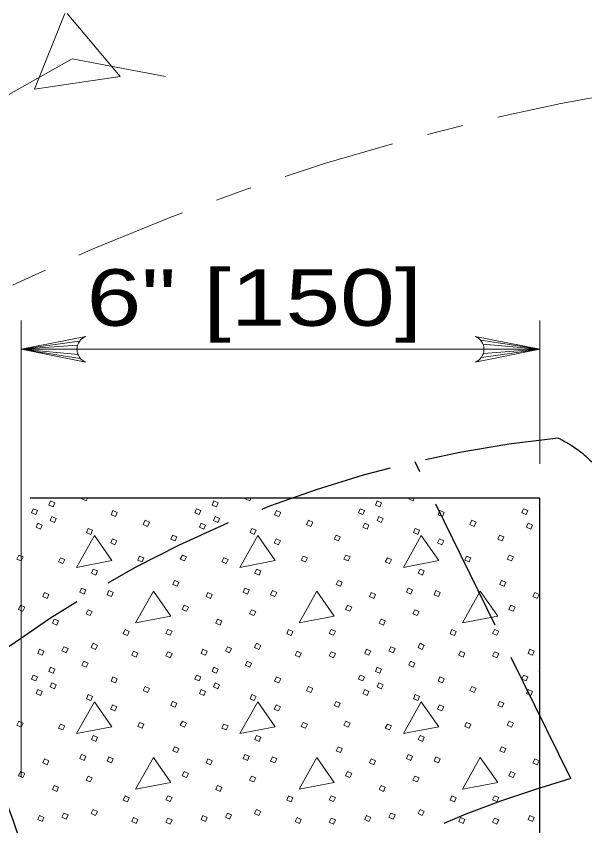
# Model space of a CAD drawing. Extents: x 1083.1 to 1117.1, y 719.4 to 741.4.
# Drawn here: x 1091.505 to 1093.074, y 727.471 to 729.705 of the extents above; entities that cross this region are included whole.
import ezdxf

# ---------------------------------------------------------------- set-up
doc = ezdxf.new("R2010")
doc.units = 0
doc.header["$LTSCALE"] = 0.062
doc.linetypes.add('DOT_DASHED', pattern=[7.7, 5, -1.2, 0.3, -1.2])
doc.linetypes.add('LONG_DASHED', pattern=[7.5, 6, -1.5])
doc.layers.add('1', color=7, linetype='Continuous', lineweight=13)

msp = doc.modelspace()

# ---------------------------------------------------------------- linework, layer by layer
at = {"layer": '1'}
for p, q in [((1091.65942, 729.58758), (1091.43975, 729.46433)), ((1091.65942, 729.58758), (1091.91658, 729.53892)), ((1091.51858, 727.60667), (1091.51858, 728.86525)), ((1092.94983, 728.47042), (1092.94983, 728.86525)), ((1091.67975, 728.80867), (1091.51858, 728.78608)), ((1091.67433, 728.7975), (1091.51858, 728.78608)), ((1092.78675, 728.811), (1092.94983, 728.78608)), ((1092.79292, 728.80058), (1092.94983, 728.78608)), ((1091.51858, 728.78608), (1092.94983, 728.78608)), ((1091.67267, 728.78608), (1091.51858, 728.78608)), ((1091.6755, 728.77167), (1091.51858, 728.78608)), ((1091.68167, 728.76117), (1091.51858, 728.78608)), ((1092.78867, 728.76358), (1092.94983, 728.78608)), ((1092.79408, 728.77475), (1092.94983, 728.78608)), ((1092.79575, 728.78608), (1092.94983, 728.78608))]:
    msp.add_line(p, q, dxfattribs=at)
at = {"layer": '1', "linetype": 'LONG_DASHED', "lineweight": 25}
msp.add_line((1093.0355, 727.60142), (1092.6055, 728.47533), dxfattribs=at)
at = {"layer": '1', "lineweight": 25}
msp.add_line((1092.94983, 728.3755), (1091.54342, 728.3755), dxfattribs=at)
at = {"layer": '1'}
for points in [[(1091.63858, 729.71292), (1091.55517, 729.50408), (1091.79142, 729.53892), (1091.6455, 729.71292)], [(1091.69667, 728.7505), (1091.51858, 728.78608), (1091.69667, 728.82175)], [(1092.77175, 728.82175), (1092.94983, 728.78608), (1092.77175, 728.7505)], [(1091.7015, 728.3755), (1091.69825, 728.368), (1091.68633, 728.3735), (1091.68725, 728.3755)], [(1092.1525, 728.3755), (1092.14925, 728.368), (1092.13742, 728.3735), (1092.13825, 728.3755)], [(1092.60358, 728.3755), (1092.60033, 728.368), (1092.58842, 728.3735), (1092.58933, 728.3755)], [(1092.94983, 728.35525), (1092.94767, 728.35608), (1092.94983, 728.3615)], [(1092.94983, 727.89633), (1092.94767, 727.89717), (1092.94983, 727.90258)]]:
    msp.add_lwpolyline(points, dxfattribs=at)
at = {"layer": '1', "lineweight": 25}
msp.add_lwpolyline([(1091.51858, 727.42125), (1092.94983, 727.42125), (1092.94983, 728.3755)], dxfattribs=at)
at = {"layer": '1'}
for points in [[(1091.59933, 728.368), (1091.61117, 728.36242), (1091.60642, 728.35133), (1091.59458, 728.35608)], [(1092.05033, 728.368), (1092.06225, 728.36242), (1092.0575, 728.35133), (1092.04558, 728.35608)], [(1092.50142, 728.368), (1092.51325, 728.36242), (1092.5085, 728.35133), (1092.49667, 728.35608)], [(1091.55183, 728.34583), (1091.56367, 728.34108), (1091.55892, 728.33), (1091.54708, 728.33475)], [(1091.77183, 728.34108), (1091.78367, 728.3355), (1091.77892, 728.32442), (1091.76708, 728.32917)], [(1092.00283, 728.34583), (1092.01475, 728.34108), (1092.01, 728.33), (1091.99817, 728.33475)], [(1092.22283, 728.34108), (1092.23475, 728.3355), (1092.23, 728.32442), (1092.21808, 728.32917)], [(1092.45392, 728.34583), (1092.46575, 728.34108), (1092.461, 728.33), (1092.44917, 728.33475)], [(1092.67392, 728.34108), (1092.68575, 728.3355), (1092.681, 728.32442), (1092.66917, 728.32917)], [(1092.90492, 728.34583), (1092.91683, 728.34108), (1092.91208, 728.33), (1092.90017, 728.33475)], [(1091.5645, 728.30625), (1091.57633, 728.30075), (1091.57158, 728.28967), (1091.55975, 728.29517)], [(1091.60325, 728.32442), (1091.61517, 728.31892), (1091.61042, 728.30783), (1091.5985, 728.31333)], [(1091.86042, 728.31417), (1091.87233, 728.30942), (1091.86675, 728.29758), (1091.85492, 728.30308)], [(1092.0155, 728.30625), (1092.02742, 728.30075), (1092.02267, 728.28967), (1092.01075, 728.29517)], [(1092.05433, 728.32442), (1092.06617, 728.31892), (1092.06142, 728.30783), (1092.04958, 728.31333)], [(1092.3115, 728.31417), (1092.32333, 728.30942), (1092.31783, 728.29758), (1092.30592, 728.30308)], [(1092.46658, 728.30625), (1092.47842, 728.30075), (1092.47367, 728.28967), (1092.46183, 728.29517)], [(1092.50533, 728.32442), (1092.51725, 728.31892), (1092.5125, 728.30783), (1092.50058, 728.31333)], [(1092.7625, 728.31417), (1092.77442, 728.30942), (1092.76883, 728.29758), (1092.757, 728.30308)], [(1092.91758, 728.30625), (1092.9295, 728.30075), (1092.92475, 728.28967), (1092.91283, 728.29517)], [(1091.70375, 728.292), (1091.71567, 728.28725), (1091.71092, 728.27542), (1091.699, 728.28092)], [(1092.15483, 728.292), (1092.16667, 728.28725), (1092.16192, 728.27542), (1092.15008, 728.28092)], [(1092.60583, 728.292), (1092.61767, 728.28725), (1092.613, 728.27542), (1092.60108, 728.28092)], [(1091.72042, 728.27225), (1091.67133, 728.18442), (1091.76867, 728.20342)], [(1091.771, 728.2635), (1091.78292, 728.258), (1091.77733, 728.24692), (1091.7655, 728.25167)], [(1091.93642, 728.273), (1091.94825, 728.26825), (1091.9435, 728.25717), (1091.93167, 728.26192)], [(1092.17142, 728.27225), (1092.12233, 728.18442), (1092.21967, 728.20342)], [(1092.22208, 728.2635), (1092.23392, 728.258), (1092.22842, 728.24692), (1092.2165, 728.25167)], [(1092.38742, 728.273), (1092.39933, 728.26825), (1092.39458, 728.25717), (1092.38267, 728.26192)], [(1092.62242, 728.27225), (1092.57342, 728.18442), (1092.67075, 728.20342)], [(1092.67308, 728.2635), (1092.685, 728.258), (1092.67942, 728.24692), (1092.66758, 728.25167)], [(1092.8385, 728.273), (1092.85033, 728.26825), (1092.84558, 728.25717), (1092.83375, 728.26192)], [(1091.51225, 728.21842), (1091.52417, 728.21367), (1091.51858, 728.20258), (1091.50675, 728.20733)], [(1091.96333, 728.21842), (1091.97517, 728.21367), (1091.96967, 728.20258), (1091.95775, 728.20733)], [(1092.41433, 728.21842), (1092.42625, 728.21367), (1092.42067, 728.20258), (1092.40883, 728.20733)], [(1092.86542, 728.21842), (1092.87725, 728.21367), (1092.87175, 728.20258), (1092.85983, 728.20733)], [(1091.627, 728.2105), (1091.63883, 728.20575), (1091.63333, 728.19467), (1091.6215, 728.19942)], [(1091.84542, 728.21525), (1091.85725, 728.2105), (1091.8525, 728.19942), (1091.84067, 728.20417)], [(1092.07808, 728.2105), (1092.08992, 728.20575), (1092.08442, 728.19467), (1092.0725, 728.19942)], [(1092.29642, 728.21525), (1092.30833, 728.2105), (1092.30358, 728.19942), (1092.29167, 728.20417)], [(1092.52908, 728.2105), (1092.54092, 728.20575), (1092.53542, 728.19467), (1092.5235, 728.19942)], [(1092.7475, 728.21525), (1092.75933, 728.2105), (1092.75458, 728.19942), (1092.74275, 728.20417)], [(1091.71725, 728.17967), (1091.72908, 728.17492), (1091.72433, 728.163), (1091.7125, 728.16858)], [(1092.16825, 728.17967), (1092.18008, 728.17492), (1092.17533, 728.163), (1092.1635, 728.16858)], [(1092.61925, 728.17967), (1092.63117, 728.17492), (1092.62642, 728.163), (1092.61458, 728.16858)], [(1091.94192, 728.148), (1091.95383, 728.14325), (1091.94908, 728.13217), (1091.93717, 728.13692)], [(1092.393, 728.148), (1092.40483, 728.14325), (1092.40008, 728.13217), (1092.38825, 728.13692)], [(1092.844, 728.148), (1092.85592, 728.14325), (1092.85117, 728.13217), (1092.83925, 728.13692)], [(1091.58267, 728.11475), (1091.59458, 728.10925), (1091.58983, 728.09817), (1091.57792, 728.10367)], [(1091.68475, 728.12667), (1091.69667, 728.12192), (1091.69192, 728.11), (1091.68, 728.11558)], [(1091.76075, 728.12033), (1091.77258, 728.11475), (1091.76783, 728.10367), (1091.756, 728.10842)], [(1091.88342, 728.11875), (1091.83433, 728.03092), (1091.93167, 728.04992)], [(1092.03375, 728.11475), (1092.04558, 728.10925), (1092.04083, 728.09817), (1092.029, 728.10367)], [(1092.13583, 728.12667), (1092.14767, 728.12192), (1092.14292, 728.11), (1092.13108, 728.11558)], [(1092.21175, 728.12033), (1092.22367, 728.11475), (1092.21892, 728.10367), (1092.207, 728.10842)], [(1092.33442, 728.11875), (1092.28533, 728.03092), (1092.38267, 728.04992)], [(1092.48475, 728.11475), (1092.49667, 728.10925), (1092.49192, 728.09817), (1092.48, 728.10367)], [(1092.58683, 728.12667), (1092.59875, 728.12192), (1092.594, 728.11), (1092.58208, 728.11558)], [(1092.66283, 728.12033), (1092.67467, 728.11475), (1092.66992, 728.10367), (1092.65808, 728.10842)], [(1092.7855, 728.11875), (1092.73642, 728.03092), (1092.83375, 728.04992)], [(1092.93583, 728.11475), (1092.94767, 728.10925), (1092.94292, 728.09817), (1092.93108, 728.10367)], [(1091.517, 728.08), (1091.52892, 728.07442), (1091.52333, 728.06333), (1091.5115, 728.06808)], [(1091.703, 728.06733), (1091.71483, 728.06258), (1091.70933, 728.0515), (1091.69742, 728.05625)], [(1091.96808, 728.08), (1091.97992, 728.07442), (1091.97442, 728.06333), (1091.9625, 728.06808)], [(1092.154, 728.06733), (1092.16592, 728.06258), (1092.16033, 728.0515), (1092.1485, 728.05625)], [(1092.41908, 728.08), (1092.431, 728.07442), (1092.42542, 728.06333), (1092.41358, 728.06808)], [(1092.60508, 728.06733), (1092.61692, 728.06258), (1092.61142, 728.0515), (1092.5995, 728.05625)], [(1092.87017, 728.08), (1092.882, 728.07442), (1092.8765, 728.06333), (1092.86458, 728.06808)], [(1091.60958, 728.04117), (1091.6215, 728.03642), (1091.61675, 728.02458), (1091.60483, 728.03008)], [(1092.06067, 728.04117), (1092.0725, 728.03642), (1092.06775, 728.02458), (1092.05592, 728.03008)], [(1092.51167, 728.04117), (1092.5235, 728.03642), (1092.51883, 728.02458), (1092.50692, 728.03008)], [(1091.80508, 728.01275), (1091.81692, 728.00717), (1091.81217, 727.99608), (1091.80033, 728.00083)], [(1091.92292, 728.01275), (1091.93483, 728.008), (1091.92925, 727.99692), (1091.91742, 728.00167)], [(1092.25608, 728.01275), (1092.26792, 728.00717), (1092.26325, 727.99608), (1092.25133, 728.00083)], [(1092.374, 728.01275), (1092.38583, 728.008), (1092.38033, 727.99692), (1092.36842, 728.00167)], [(1092.70708, 728.01275), (1092.719, 728.00717), (1092.71425, 727.99608), (1092.70233, 728.00083)], [(1092.825, 728.01275), (1092.83692, 728.008), (1092.83133, 727.99692), (1092.8195, 728.00167)], [(1091.71725, 727.97475), (1091.72908, 727.96917), (1091.72358, 727.95808), (1091.71167, 727.96367)], [(1092.16825, 727.97475), (1092.18008, 727.96917), (1092.17458, 727.95808), (1092.16275, 727.96367)], [(1092.61925, 727.97475), (1092.63117, 727.96917), (1092.62558, 727.95808), (1092.61375, 727.96367)], [(1091.56925, 727.95892), (1091.58108, 727.95333), (1091.57633, 727.94225), (1091.5645, 727.947)], [(1091.6365, 727.96525), (1091.64833, 727.9605), (1091.64283, 727.94858), (1091.631, 727.95417)], [(1091.82875, 727.95333), (1091.84067, 727.94783), (1091.83592, 727.93675), (1091.824, 727.94225)], [(1091.92292, 727.951), (1091.93483, 727.94625), (1091.92925, 727.93442), (1091.91742, 727.93992)], [(1092.02025, 727.95892), (1092.03217, 727.95333), (1092.02742, 727.94225), (1092.0155, 727.947)], [(1092.0875, 727.96525), (1092.09942, 727.9605), (1092.09383, 727.94858), (1092.082, 727.95417)], [(1092.27983, 727.95333), (1092.29167, 727.94783), (1092.28692, 727.93675), (1092.27508, 727.94225)], [(1092.374, 727.951), (1092.38583, 727.94625), (1092.38033, 727.93442), (1092.36842, 727.93992)], [(1092.47133, 727.95892), (1092.48317, 727.95333), (1092.47842, 727.94225), (1092.46658, 727.947)], [(1092.53858, 727.96525), (1092.55042, 727.9605), (1092.54492, 727.94858), (1092.533, 727.95417)], [(1092.73083, 727.95333), (1092.74275, 727.94783), (1092.738, 727.93675), (1092.72608, 727.94225)], [(1092.825, 727.951), (1092.83692, 727.94625), (1092.83133, 727.93442), (1092.8195, 727.93992)], [(1092.92233, 727.95892), (1092.93425, 727.95333), (1092.9295, 727.94225), (1092.91758, 727.947)], [(1091.69108, 727.92567), (1091.703, 727.92017), (1091.69825, 727.90908), (1091.68633, 727.91458)], [(1092.14217, 727.92567), (1092.154, 727.92017), (1092.14925, 727.90908), (1092.13742, 727.91458)], [(1092.59317, 727.92567), (1092.60508, 727.92017), (1092.60033, 727.90908), (1092.58842, 727.91458)], [(1091.59933, 727.90908), (1091.61117, 727.9035), (1091.60642, 727.89242), (1091.59458, 727.89717)], [(1092.05033, 727.90908), (1092.06225, 727.9035), (1092.0575, 727.89242), (1092.04558, 727.89717)], [(1092.50142, 727.90908), (1092.51325, 727.9035), (1092.5085, 727.89242), (1092.49667, 727.89717)], [(1091.55183, 727.88692), (1091.56367, 727.88217), (1091.55892, 727.87108), (1091.54708, 727.87583)], [(1091.77183, 727.88217), (1091.78367, 727.87658), (1091.77892, 727.86558), (1091.76708, 727.87025)], [(1092.00283, 727.88692), (1092.01475, 727.88217), (1092.01, 727.87108), (1091.99817, 727.87583)], [(1092.22283, 727.88217), (1092.23475, 727.87658), (1092.23, 727.86558), (1092.21808, 727.87025)], [(1092.45392, 727.88692), (1092.46575, 727.88217), (1092.461, 727.87108), (1092.44917, 727.87583)], [(1092.67392, 727.88217), (1092.68575, 727.87658), (1092.681, 727.86558), (1092.66917, 727.87025)], [(1092.90492, 727.88692), (1092.91683, 727.88217), (1092.91208, 727.87108), (1092.90017, 727.87583)], [(1091.60325, 727.86558), (1091.61517, 727.86), (1091.61042, 727.84892), (1091.5985, 727.8545)], [(1092.05433, 727.86558), (1092.06617, 727.86), (1092.06142, 727.84892), (1092.04958, 727.8545)], [(1092.50533, 727.86558), (1092.51725, 727.86), (1092.5125, 727.84892), (1092.50058, 727.8545)], [(1091.5645, 727.84733), (1091.57633, 727.84183), (1091.57158, 727.83075), (1091.55975, 727.83625)], [(1091.86042, 727.85525), (1091.87233, 727.8505), (1091.86675, 727.83867), (1091.85492, 727.84417)], [(1092.0155, 727.84733), (1092.02742, 727.84183), (1092.02267, 727.83075), (1092.01075, 727.83625)], [(1092.3115, 727.85525), (1092.32333, 727.8505), (1092.31783, 727.83867), (1092.30592, 727.84417)], [(1092.46658, 727.84733), (1092.47842, 727.84183), (1092.47367, 727.83075), (1092.46183, 727.83625)], [(1092.7625, 727.85525), (1092.77442, 727.8505), (1092.76883, 727.83867), (1092.757, 727.84417)], [(1092.91758, 727.84733), (1092.9295, 727.84183), (1092.92475, 727.83075), (1092.91283, 727.83625)], [(1091.70375, 727.83308), (1091.71567, 727.82833), (1091.71092, 727.8165), (1091.699, 727.822)], [(1091.93642, 727.81408), (1091.94825, 727.80933), (1091.9435, 727.79833), (1091.93167, 727.803)], [(1092.15483, 727.83308), (1092.16667, 727.82833), (1092.16192, 727.8165), (1092.15008, 727.822)], [(1092.38742, 727.81408), (1092.39933, 727.80933), (1092.39458, 727.79833), (1092.38267, 727.803)], [(1092.60583, 727.83308), (1092.61767, 727.82833), (1092.613, 727.8165), (1092.60108, 727.822)], [(1092.8385, 727.81408), (1092.85033, 727.80933), (1092.84558, 727.79833), (1092.83375, 727.803)], [(1091.72042, 727.81333), (1091.67133, 727.7255), (1091.76867, 727.7445)], [(1091.771, 727.80458), (1091.78292, 727.79908), (1091.77733, 727.788), (1091.7655, 727.79275)], [(1092.17142, 727.81333), (1092.12233, 727.7255), (1092.21967, 727.7445)], [(1092.22208, 727.80458), (1092.23392, 727.79908), (1092.22842, 727.788), (1092.2165, 727.79275)], [(1092.62242, 727.81333), (1092.57342, 727.7255), (1092.67075, 727.7445)], [(1092.67308, 727.80458), (1092.685, 727.79908), (1092.67942, 727.788), (1092.66758, 727.79275)], [(1091.51225, 727.7595), (1091.52417, 727.75475), (1091.51858, 727.74367), (1091.50675, 727.74842)], [(1091.627, 727.75158), (1091.63883, 727.74683), (1091.63333, 727.73575), (1091.6215, 727.7405)], [(1091.84542, 727.75633), (1091.85725, 727.75158), (1091.8525, 727.7405), (1091.84067, 727.74525)], [(1091.96333, 727.7595), (1091.97517, 727.75475), (1091.96967, 727.74367), (1091.95775, 727.74842)], [(1092.07808, 727.75158), (1092.08992, 727.74683), (1092.08442, 727.73575), (1092.0725, 727.7405)], [(1092.29642, 727.75633), (1092.30833, 727.75158), (1092.30358, 727.7405), (1092.29167, 727.74525)], [(1092.41433, 727.7595), (1092.42625, 727.75475), (1092.42067, 727.74367), (1092.40883, 727.74842)], [(1092.52908, 727.75158), (1092.54092, 727.74683), (1092.53542, 727.73575), (1092.5235, 727.7405)], [(1092.7475, 727.75633), (1092.75933, 727.75158), (1092.75458, 727.7405), (1092.74275, 727.74525)], [(1092.86542, 727.7595), (1092.87725, 727.75475), (1092.87175, 727.74367), (1092.85983, 727.74842)], [(1091.71725, 727.72075), (1091.72908, 727.716), (1091.72433, 727.70417), (1091.7125, 727.70967)], [(1092.16825, 727.72075), (1092.18008, 727.716), (1092.17533, 727.70417), (1092.1635, 727.70967)], [(1092.61925, 727.72075), (1092.63117, 727.716), (1092.62642, 727.70417), (1092.61458, 727.70967)], [(1091.94192, 727.68908), (1091.95383, 727.68433), (1091.94908, 727.67325), (1091.93717, 727.678)], [(1092.393, 727.68908), (1092.40483, 727.68433), (1092.40008, 727.67325), (1092.38825, 727.678)], [(1092.844, 727.68908), (1092.85592, 727.68433), (1092.85117, 727.67325), (1092.83925, 727.678)], [(1091.68475, 727.66775), (1091.69667, 727.663), (1091.69192, 727.65117), (1091.68, 727.65667)], [(1091.76075, 727.66142), (1091.77258, 727.65583), (1091.76783, 727.64483), (1091.756, 727.6495)], [(1091.88342, 727.65983), (1091.83433, 727.572), (1091.93167, 727.591)], [(1092.13583, 727.66775), (1092.14767, 727.663), (1092.14292, 727.65117), (1092.13108, 727.65667)], [(1092.21175, 727.66142), (1092.22367, 727.65583), (1092.21892, 727.64483), (1092.207, 727.6495)], [(1092.33442, 727.65983), (1092.28533, 727.572), (1092.38267, 727.591)], [(1092.58683, 727.66775), (1092.59875, 727.663), (1092.594, 727.65117), (1092.58208, 727.65667)], [(1092.66283, 727.66142), (1092.67467, 727.65583), (1092.66992, 727.64483), (1092.65808, 727.6495)], [(1092.7855, 727.65983), (1092.73642, 727.572), (1092.83375, 727.591)], [(1091.58267, 727.65583), (1091.59458, 727.65033), (1091.58983, 727.63925), (1091.57792, 727.64483)], [(1092.03375, 727.65583), (1092.04558, 727.65033), (1092.04083, 727.63925), (1092.029, 727.64483)], [(1092.48475, 727.65583), (1092.49667, 727.65033), (1092.49192, 727.63925), (1092.48, 727.64483)], [(1092.93583, 727.65583), (1092.94767, 727.65033), (1092.94292, 727.63925), (1092.93108, 727.64483)], [(1091.517, 727.62108), (1091.52892, 727.6155), (1091.52333, 727.60442), (1091.5115, 727.60917)], [(1091.96808, 727.62108), (1091.97992, 727.6155), (1091.97442, 727.60442), (1091.9625, 727.60917)], [(1092.41908, 727.62108), (1092.431, 727.6155), (1092.42542, 727.60442), (1092.41358, 727.60917)], [(1092.87017, 727.62108), (1092.882, 727.6155), (1092.8765, 727.60442), (1092.86458, 727.60917)], [(1091.703, 727.60842), (1091.71483, 727.60367), (1091.70933, 727.59258), (1091.69742, 727.59733)], [(1092.154, 727.60842), (1092.16592, 727.60367), (1092.16033, 727.59258), (1092.1485, 727.59733)], [(1092.60508, 727.60842), (1092.61692, 727.60367), (1092.61142, 727.59258), (1092.5995, 727.59733)], [(1091.60958, 727.58225), (1091.6215, 727.57758), (1091.61675, 727.56567), (1091.60483, 727.57125)], [(1092.06067, 727.58225), (1092.0725, 727.57758), (1092.06775, 727.56567), (1092.05592, 727.57125)], [(1092.51167, 727.58225), (1092.5235, 727.57758), (1092.51883, 727.56567), (1092.50692, 727.57125)], [(1091.80508, 727.55383), (1091.81692, 727.54825), (1091.81217, 727.53717), (1091.80033, 727.54192)], [(1091.92292, 727.55383), (1091.93483, 727.54908), (1091.92925, 727.538), (1091.91742, 727.54275)], [(1092.25608, 727.55383), (1092.26792, 727.54825), (1092.26325, 727.53717), (1092.25133, 727.54192)], [(1092.374, 727.55383), (1092.38583, 727.54908), (1092.38033, 727.538), (1092.36842, 727.54275)], [(1092.70708, 727.55383), (1092.719, 727.54825), (1092.71425, 727.53717), (1092.70233, 727.54192)], [(1092.825, 727.55383), (1092.83692, 727.54908), (1092.83133, 727.538), (1092.8195, 727.54275)], [(1091.6365, 727.50633), (1091.64833, 727.50158), (1091.64283, 727.48975), (1091.631, 727.49525)], [(1091.71725, 727.51583), (1091.72908, 727.51033), (1091.72358, 727.49925), (1091.71167, 727.50475)], [(1092.0875, 727.50633), (1092.09942, 727.50158), (1092.09383, 727.48975), (1092.082, 727.49525)], [(1092.16825, 727.51583), (1092.18008, 727.51033), (1092.17458, 727.49925), (1092.16275, 727.50475)], [(1092.53858, 727.50633), (1092.55042, 727.50158), (1092.54492, 727.48975), (1092.533, 727.49525)], [(1092.61925, 727.51583), (1092.63117, 727.51033), (1092.62558, 727.49925), (1092.61375, 727.50475)], [(1091.56925, 727.5), (1091.58108, 727.4945), (1091.57633, 727.48342), (1091.5645, 727.48817)], [(1091.82875, 727.4945), (1091.84067, 727.48892), (1091.83592, 727.47783), (1091.824, 727.48342)], [(1091.92292, 727.49208), (1091.93483, 727.48733), (1091.92925, 727.4755), (1091.91742, 727.481)], [(1092.02025, 727.5), (1092.03217, 727.4945), (1092.02742, 727.48342), (1092.0155, 727.48817)], [(1092.27983, 727.4945), (1092.29167, 727.48892), (1092.28692, 727.47783), (1092.27508, 727.48342)], [(1092.374, 727.49208), (1092.38583, 727.48733), (1092.38033, 727.4755), (1092.36842, 727.481)], [(1092.47133, 727.5), (1092.48317, 727.4945), (1092.47842, 727.48342), (1092.46658, 727.48817)], [(1092.73083, 727.4945), (1092.74275, 727.48892), (1092.738, 727.47783), (1092.72608, 727.48342)], [(1092.825, 727.49208), (1092.83692, 727.48733), (1092.83133, 727.4755), (1092.8195, 727.481)], [(1092.92233, 727.5), (1092.93425, 727.4945), (1092.9295, 727.48342), (1092.91758, 727.48817)]]:
    msp.add_lwpolyline(points, close=True, dxfattribs=at)
at = {"layer": '1', "linetype": 'LONG_DASHED', "lineweight": 25}
for centre, major_axis, start_param, end_param in [((1093.49182, 725.47113), (-5.00454, 0), 4.8336378, 5.5182036), ((1093.31535, 725.42846), (-3.12878, 0), 4.813028, 5.5118541), ((1093.89814, 724.59428), (-3.12878, 0), 4.9917247, 5.5118541)]:
    msp.add_ellipse(centre, major_axis=major_axis, ratio=0.999895, start_param=start_param, end_param=end_param, dxfattribs=at)
at = {"layer": '1', "linetype": 'DOT_DASHED'}
msp.add_ellipse((1094.28973, 723.05616), major_axis=(-6.53582, 0), ratio=0.999895, start_param=4.7028731, end_param=5.2539695, dxfattribs=at)
at = {"layer": '1'}
for centre, major_axis in [((1091.71109, 728.78612), (-0.03843, 0)), ((1092.75732, 728.78612), (0.03843, 0))]:
    msp.add_ellipse(centre, major_axis=major_axis, ratio=0.999895, start_param=5.0978942, end_param=7.4685073, dxfattribs=at)
at = {"layer": '1', "lineweight": 25}
msp.add_ellipse((1088.70626, 726.4909), major_axis=(2.96229, 0), ratio=0.999895, start_param=0.3195205, end_param=0.6896388, dxfattribs=at)
at = {"layer": '1', "linetype": 'LONG_DASHED', "lineweight": 25}
msp.add_spline([(1093.001, 728.54108), (1093.03775, 728.52058), (1093.10333, 728.46517), (1093.15725, 728.38992), (1093.22933, 728.27942), (1093.35042, 728.24308), (1093.484, 728.233), (1093.767, 728.237)], degree=3, dxfattribs=at)

# ---------------------------------------------------------------- texts
at = {"layer": '1', "width": 1.3}
msp.add_text('6" [150]', height=0.156, dxfattribs=at).set_placement((1091.69925, 728.85108))

doc.saveas('drawing.dxf')
